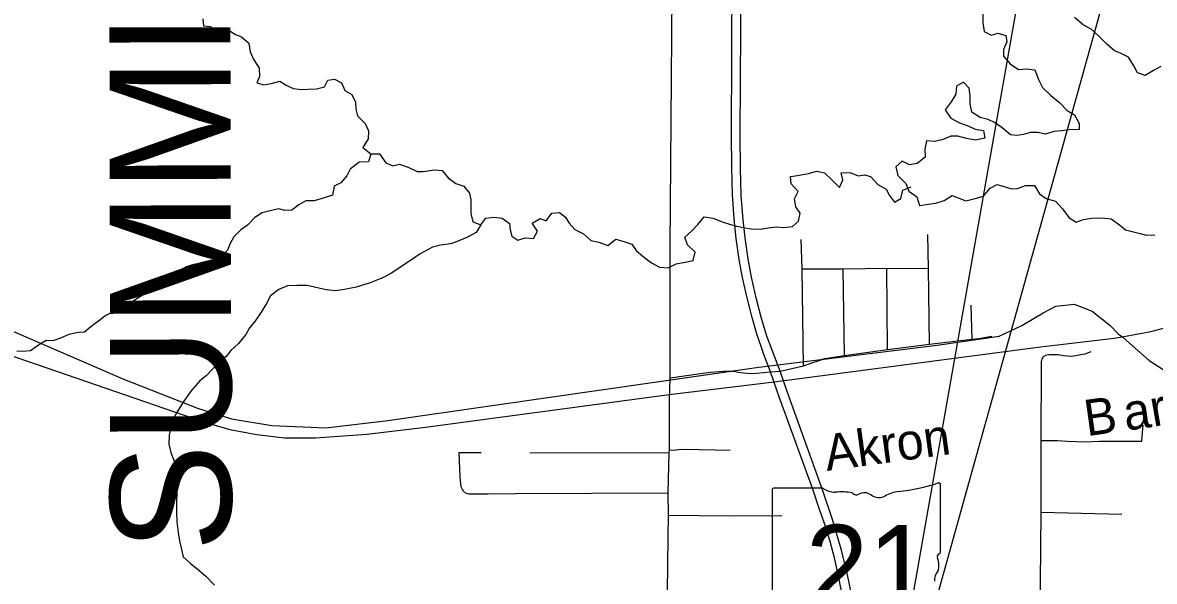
# Model space of a CAD drawing. Extents: x 0 to 34, y -5 to 22.
# Drawn here: x 4.064 to 5.836, y 18.02 to 18.894 of the extents above; entities that cross this region are included whole.
import ezdxf

# ---------------------------------------------------------------- set-up
doc = ezdxf.new("R2010")
doc.units = 0
for name, color, linetype in [('GM_X_City_Street', 7, 'Continuous'), ('GM_X_County_Road', 7, 'Continuous'), ('GM_X_County_Text', 7, 'Continuous'), ('GM_X_Major_Lake', 7, 'Continuous'), ('GM_X_Minor_River', 7, 'Continuous'), ('GM_X_Rail_Line', 7, 'Continuous'), ('GM_X_Rail_Line_Text', 7, 'Continuous'), ('GM_X_State_Location', 7, 'Continuous'), ('GM_X_State_Route', 7, 'Continuous'), ('GM_X_State_Shield', 7, 'Continuous'), ('SH_Text', 7, 'Continuous')]:
    doc.layers.add(name, color=color, linetype=linetype)

msp = doc.modelspace()

# ---------------------------------------------------------------- linework, layer by layer
at = {"layer": 'GM_X_City_Street'}
for p, q in [((5.3507, 18.3734), (5.3486, 18.5091)), ((5.4178, 18.3829), (5.4166, 18.5098)), ((5.5482, 18.452), (5.5499, 18.399)), ((4.7473, 18.2216), (4.7817, 18.2216)), ((4.8577, 18.2212), (5.076, 18.2214)), ((5.6581, 18.1281), (5.7846, 18.1252))]:
    msp.add_line(p, q, dxfattribs=at)
for points in [[(5.2863, 18.3573), (5.2842, 18.5091), (5.2828, 18.5548)], [(5.4836, 18.3912), (5.4822, 18.5096), (5.4807, 18.5626)], [(5.2842, 18.5091), (5.3486, 18.5091), (5.4166, 18.5098), (5.4822, 18.5096)], [(5.0777, 18.3384), (5.1213, 18.3448), (5.1409, 18.3474), (5.1542, 18.3483), (5.1618, 18.3488), (5.1686, 18.3486), (5.1771, 18.3486), (5.1847, 18.3474), (5.1923, 18.3464), (5.203, 18.345), (5.2127, 18.3455), (5.2346, 18.3475), (5.2498, 18.349), (5.2863, 18.3573), (5.2991, 18.3618), (5.3093, 18.3651), (5.3195, 18.3685), (5.3507, 18.3734), (5.4178, 18.3829), (5.4836, 18.3912), (5.5499, 18.399), (5.5608, 18.3999), (5.5809, 18.4033)], [(5.656, 17.6203), (5.6561, 17.7219), (5.6565, 17.8103), (5.6565, 17.9139), (5.6572, 18.0186), (5.6581, 18.1281), (5.6584, 18.2401), (5.6588, 18.359), (5.6591, 18.364), (5.66, 18.3682), (5.6621, 18.3715)], [(5.6621, 18.3715), (5.6657, 18.3737), (5.6702, 18.3751), (5.6771, 18.3751), (5.6851, 18.3746), (5.6932, 18.3734), (5.6993, 18.373), (5.7052, 18.3725), (5.7124, 18.3734), (5.7206, 18.3746), (5.727, 18.376), (5.7365, 18.3796)], [(5.8161, 18.2391), (5.8163, 18.2465), (5.8182, 18.2643)], [(5.6584, 18.2401), (5.6837, 18.2401), (5.6991, 18.2391), (5.728, 18.2382), (5.7498, 18.2391), (5.8161, 18.2391)], [(4.7548, 18.16), (4.7525, 18.1634), (4.7506, 18.1679), (4.7492, 18.1773), (4.749, 18.1835), (4.7473, 18.2216)], [(5.0763, 18.2257), (5.0831, 18.2254), (5.0905, 18.2261), (5.099, 18.2266), (5.1717, 18.2249)], [(4.7548, 18.16), (4.7582, 18.1579), (4.7625, 18.157), (4.7928, 18.157), (4.8357, 18.1574), (5.0746, 18.1584)], [(5.0751, 18.1236), (5.1705, 18.1226), (5.2522, 18.1229)]]:
    msp.add_lwpolyline(points, dxfattribs=at)
at = {"layer": 'GM_X_County_Road'}
msp.add_lwpolyline([(5.0725, 17.9168), (5.0746, 18.0892), (5.0751, 18.1236), (5.0746, 18.1584), (5.076, 18.2214), (5.0763, 18.2257), (5.0765, 18.3047), (5.0777, 18.3384), (5.0777, 18.5427), (5.0793, 18.7403), (5.0805, 18.9401), (5.0808, 19.1246), (5.081, 19.4273), (5.0819, 19.5963), (5.0824, 19.6307), (5.0824, 19.8505), (5.0836, 20.0558), (5.0846, 20.0998), (5.0842, 20.1129), (5.0864, 20.3819), (5.0857, 20.5652), (5.085, 20.7499), (5.0856, 20.9)], dxfattribs=at)
at = {"layer": 'GM_X_Major_Lake'}
for points in [[(5.5671, 18.9078), (5.5671, 18.8941), (5.5691, 18.8801), (5.5801, 18.8744), (5.5907, 18.8775), (5.6029, 18.8738), (5.6048, 18.8643), (5.5996, 18.8521), (5.5993, 18.8418), (5.6099, 18.8297), (5.6229, 18.8207), (5.6361, 18.8219), (5.6486, 18.8205), (5.654, 18.8053), (5.6605, 18.7924), (5.6727, 18.7807), (5.6876, 18.7686), (5.699, 18.7565), (5.7104, 18.7501), (5.7177, 18.7365), (5.7177, 18.7266), (5.7056, 18.7269), (5.6904, 18.7249), (5.6779, 18.7237), (5.6651, 18.7198), (5.6537, 18.7224), (5.6415, 18.722), (5.6309, 18.7192), (5.62, 18.7173), (5.6105, 18.7187), (5.5972, 18.7293), (5.5861, 18.7376), (5.5755, 18.7425), (5.5626, 18.7458), (5.5496, 18.7541), (5.5473, 18.767), (5.5472, 18.7796), (5.5457, 18.7914), (5.5365, 18.8012), (5.5256, 18.7947), (5.5249, 18.7821), (5.5173, 18.7703), (5.5083, 18.7577), (5.5167, 18.7448), (5.5304, 18.7373), (5.5452, 18.7324), (5.5551, 18.7275), (5.568, 18.7253), (5.5703, 18.7132), (5.5556, 18.7104), (5.5415, 18.713), (5.5279, 18.7164), (5.5169, 18.7163), (5.5036, 18.7105), (5.4907, 18.7082), (5.4786, 18.7092), (5.476, 18.6963), (5.4768, 18.6834), (5.464, 18.6738), (5.4523, 18.6714), (5.4409, 18.6775), (5.4307, 18.6686), (5.4341, 18.655), (5.4463, 18.6425), (5.4513, 18.6304), (5.4639, 18.6217), (5.4677, 18.608), (5.4814, 18.61), (5.4935, 18.6116), (5.5064, 18.6159), (5.5188, 18.6239), (5.5283, 18.6202), (5.5405, 18.6153)], [(5.8457, 18.8254), (5.8344, 18.8193), (5.8212, 18.8116), (5.809, 18.8157), (5.8036, 18.8267), (5.7952, 18.8399), (5.7827, 18.8463), (5.7732, 18.8501), (5.761, 18.8603), (5.7477, 18.8739), (5.7366, 18.8841), (5.7241, 18.8909), (5.7104, 18.9022)], [(5.5405, 18.6153), (5.5549, 18.6188), (5.5681, 18.6227), (5.5787, 18.6349), (5.5896, 18.6411), (5.6022, 18.6373), (5.6117, 18.634), (5.6211, 18.6344), (5.634, 18.6394), (5.648, 18.6391), (5.6557, 18.6262), (5.6663, 18.6187), (5.6807, 18.615), (5.6918, 18.6029), (5.7017, 18.5892), (5.7131, 18.5821), (5.7245, 18.5859), (5.737, 18.5883), (5.7472, 18.5887), (5.7582, 18.5884), (5.7681, 18.587), (5.781, 18.5775), (5.7905, 18.57), (5.803, 18.567), (5.8133, 18.5644), (5.8232, 18.5618), (5.8364, 18.5619)]]:
    msp.add_lwpolyline(points, dxfattribs=at)
at = {"layer": 'GM_X_Minor_River'}
for points in [[(4.3461, 18.8999), (4.347, 18.8893), (4.3587, 18.8879), (4.3629, 18.8784), (4.3732, 18.8735), (4.3837, 18.8846), (4.3971, 18.8755), (4.4066, 18.8718), (4.418, 18.862), (4.4203, 18.8483), (4.4261, 18.8358), (4.4341, 18.8229), (4.4345, 18.81), (4.4304, 18.8001), (4.4414, 18.7967), (4.4528, 18.7987), (4.4664, 18.8026), (4.4767, 18.7965), (4.4873, 18.7913), (4.5006, 18.7895), (4.5104, 18.7899), (4.5241, 18.7904), (4.5366, 18.7935), (4.5418, 18.8042), (4.5524, 18.8057), (4.5631, 18.8001), (4.5685, 18.788), (4.5791, 18.7819), (4.5852, 18.7698), (4.5853, 18.7588), (4.5884, 18.7482), (4.6002, 18.7364), (4.6052, 18.7247), (4.6048, 18.7125), (4.5966, 18.6988), (4.6091, 18.689), (4.6224, 18.6887), (4.6323, 18.675), (4.6437, 18.6702), (4.6539, 18.6729), (4.6684, 18.6673), (4.6813, 18.6613), (4.6908, 18.6613), (4.7089, 18.6637), (4.7207, 18.663), (4.7302, 18.6513), (4.742, 18.6426), (4.7546, 18.6385), (4.7633, 18.6275), (4.7657, 18.6169), (4.7657, 18.6062), (4.7654, 18.5956), (4.7689, 18.5827), (4.781, 18.5778), (4.7889, 18.5881), (4.8014, 18.5897), (4.8147, 18.5883), (4.8261, 18.5796), (4.8273, 18.5701), (4.8296, 18.5602), (4.8391, 18.5538)], [(4.6091, 18.689), (4.6054, 18.6764), (4.5906, 18.6756), (4.5766, 18.6648), (4.5714, 18.6545), (4.562, 18.6435), (4.5518, 18.6381), (4.5488, 18.624), (4.5344, 18.6193), (4.5204, 18.6151), (4.5075, 18.6154), (4.4962, 18.6092), (4.4852, 18.6008), (4.4742, 18.6004), (4.4648, 18.6026), (4.4492, 18.5991), (4.439, 18.5967), (4.4273, 18.5891), (4.416, 18.5772), (4.4054, 18.5699), (4.3948, 18.5592), (4.3888, 18.5485), (4.3847, 18.5379), (4.3749, 18.5272), (4.3605, 18.521), (4.3488, 18.519), (4.3321, 18.5159), (4.32, 18.512), (4.3064, 18.5043), (4.2928, 18.4932), (4.2834, 18.4837), (4.2702, 18.4745), (4.2565, 18.4702), (4.2399, 18.4602), (4.2263, 18.4495), (4.2154, 18.443), (4.2029, 18.4406), (4.1927, 18.4348), (4.1828, 18.4268), (4.1711, 18.4188), (4.1609, 18.4099), (4.1511, 18.4091), (4.1363, 18.4064), (4.1235, 18.4002), (4.1114, 18.3964), (4.1007, 18.397), (4.0905, 18.3905), (4.0762, 18.3806), (4.0644, 18.3793), (4.055, 18.3801)], [(4.8391, 18.5538), (4.8505, 18.5573), (4.8634, 18.5562), (4.8698, 18.5681), (4.8617, 18.5806), (4.8742, 18.5875), (4.8837, 18.5841), (4.8924, 18.596), (4.9045, 18.5968), (4.914, 18.59), (4.9194, 18.5801), (4.9285, 18.5703), (4.9418, 18.5635), (4.9536, 18.553), (4.9661, 18.5508), (4.9798, 18.5455), (4.9923, 18.5551), (5.0037, 18.5521), (5.0177, 18.5473), (5.0246, 18.5374), (5.0352, 18.528), (5.0486, 18.5182), (5.0611, 18.5114), (5.0744, 18.5107), (5.0872, 18.5169), (5.1009, 18.5192), (5.1134, 18.522), (5.1167, 18.5349), (5.1045, 18.5466), (5.1007, 18.5584), (5.1116, 18.5683), (5.121, 18.5783), (5.1308, 18.5901), (5.1449, 18.5883), (5.1589, 18.5827), (5.1722, 18.5782), (5.1817, 18.5756), (5.1923, 18.5734), (5.2045, 18.5715), (5.2185, 18.5712), (5.231, 18.5732), (5.2439, 18.5744), (5.2553, 18.5737), (5.2689, 18.5753), (5.2787, 18.5834), (5.2813, 18.5959), (5.2744, 18.6058), (5.2721, 18.6183), (5.2781, 18.6301), (5.267, 18.6418), (5.2662, 18.6536), (5.2768, 18.6548), (5.2939, 18.658), (5.3064, 18.6618), (5.3193, 18.6589), (5.3311, 18.6475), (5.3425, 18.6362), (5.3481, 18.648), (5.345, 18.659), (5.3594, 18.6595), (5.372, 18.6542), (5.3818, 18.6562), (5.3913, 18.6532), (5.4024, 18.6407), (5.4157, 18.6336), (5.421, 18.6234), (5.429, 18.6131), (5.4389, 18.6189), (5.4418, 18.6322), (5.4547, 18.6372)], [(4.781, 18.5778), (4.7739, 18.566), (4.7595, 18.5579), (4.7466, 18.5525), (4.7342, 18.5479), (4.7183, 18.5459), (4.7054, 18.5428), (4.6865, 18.5324), (4.6729, 18.5232), (4.6544, 18.5109), (4.6415, 18.5021), (4.626, 18.4944), (4.6082, 18.4871), (4.5863, 18.4801), (4.5677, 18.4766), (4.553, 18.4746), (4.5389, 18.476), (4.5093, 18.4827), (4.493, 18.483), (4.4786, 18.4825), (4.465, 18.4767), (4.4518, 18.4664), (4.4458, 18.4546), (4.4375, 18.4412), (4.4273, 18.4263), (4.4191, 18.4164), (4.4134, 18.4061), (4.4017, 18.392), (4.39, 18.3813), (4.3825, 18.3717), (4.3719, 18.3629), (4.3606, 18.3514), (4.3512, 18.3415), (4.3414, 18.3335), (4.3274, 18.3174), (4.3154, 18.3002), (4.306, 18.2853), (4.2981, 18.2712), (4.2959, 18.2598), (4.2933, 18.2488), (4.293, 18.2343), (4.2957, 18.2214), (4.3022, 18.2055), (4.3061, 18.1945), (4.3065, 18.185), (4.3058, 18.1717), (4.3051, 18.1591), (4.3048, 18.1432), (4.3049, 18.1276), (4.3053, 18.1131), (4.3073, 18.0964), (4.3093, 18.0831), (4.3124, 18.0698), (4.3155, 18.0581), (4.3265, 18.0479), (4.3364, 18.0399), (4.3509, 18.0278), (4.3642, 18.0139)]]:
    msp.add_lwpolyline(points, dxfattribs=at)
at = {"layer": 'GM_X_Rail_Line'}
for points in [[(4.0057, 18.4294), (4.2206, 18.3367), (4.3375, 18.2907), (4.3907, 18.2743), (4.4543, 18.2638), (4.5384, 18.2599), (4.6355, 18.2717), (5.2165, 18.3551), (5.4955, 18.3893), (5.5926, 18.4037), (5.6281, 18.4201), (5.6616, 18.4398), (5.6812, 18.4503), (5.7101, 18.4536), (5.7384, 18.4424), (5.7659, 18.4208), (5.7795, 18.4068)], [(4.0092, 18.3859), (4.347, 18.2697), (4.3882, 18.2573), (4.4307, 18.2497), (4.4739, 18.2442), (4.5226, 18.2442), (4.6029, 18.2501), (4.6948, 18.2613), (5.0762, 18.3125), (5.2404, 18.3319), (5.6575, 18.3867), (5.7728, 18.4004), (5.7853, 18.4026), (5.8298, 18.4107), (5.8836, 18.4248)], [(5.7795, 18.4068), (5.7859, 18.4025), (5.7918, 18.3966), (5.8276, 18.3656), (5.871, 18.3374), (6.0377, 18.2586), (6.5899, 18.0575), (7.0082, 17.9114), (7.1542, 18.0022), (7.3134, 18.0831), (7.525, 18.1436)]]:
    msp.add_lwpolyline(points, dxfattribs=at)
at = {"layer": 'GM_X_State_Route'}
for points in [[(5.3493, 17.987), (5.34, 18.0332), (5.3347, 18.0567), (5.3279, 18.0821), (5.3185, 18.1118), (5.3115, 18.1324), (5.3009, 18.1643), (5.2488, 18.3073), (5.2346, 18.3475), (5.2242, 18.3751), (5.2128, 18.4089), (5.2061, 18.4329), (5.1974, 18.4655), (5.1907, 18.4951), (5.1855, 18.5235), (5.181, 18.5563), (5.1778, 18.5869), (5.1749, 18.6253), (5.1739, 18.6669), (5.1736, 18.7198), (5.1747, 18.9685)], [(5.3656, 17.98), (5.3554, 18.0301), (5.3456, 18.0685), (5.3317, 18.1169), (5.3159, 18.1632), (5.2606, 18.3169), (5.2498, 18.349), (5.229, 18.4035), (5.2206, 18.4313), (5.2126, 18.4613), (5.2051, 18.4956), (5.1998, 18.5243), (5.1948, 18.5575), (5.1916, 18.5857), (5.1888, 18.6241), (5.1877, 18.6657), (5.1874, 18.7186), (5.1885, 18.9673)]]:
    msp.add_lwpolyline(points, dxfattribs=at)
at = {"layer": 'GM_X_State_Shield'}
for p, q in [((5.237, 18.1623), (5.237, 17.9622)), ((5.3168, 18.1658), (5.2396, 18.1658)), ((5.5007, 18.0661), (5.5007, 18.1708)), ((5.5006, 18.0661), (5.5007, 18.0661))]:
    msp.add_line(p, q, dxfattribs=at)
for centre, radius, start, end in [((5.24, 18.1628), 0.00305, 98.1301, 188.1301), ((5.3352, 18.189), 0.0296, 231.6195, 271.1119), ((5.345, 18.0534), 0.1064, 80.4867, 94.9883), ((5.3692, 18.1638), 0.00855, 219.7921, 297.1024), ((5.3817, 18.1407), 0.0178, 54.4667, 119.1411), ((5.4424, 18.1047), 0.0563, 97.3462, 120.7689), ((5.4067, 18.4386), 0.2796, 275.8445, 288.9065), ((5.4977, 18.1712), 0.00294, 351.8621, 97.738), ((5.4046, 18.1724), 0.0214, 233.8562, 294.8282), ((5.5, 18.0584), 0.00454, 107.944, 210.337), ((5.4711, 18.0451), 0.0273, 340.033, 23.6496), ((5.4975, 18.0657), 0.00314, 289.6038, 7.7341), ((5.5112, 18.0223), 0.0198, 136.8065, 186.9296)]:
    msp.add_arc(centre, radius, start, end, dxfattribs=at)
at = {"layer": 'SH_Text'}
msp.add_lwpolyline([(5.7495, 19.6552), (5.3906, 17.6203), (5.7495, 18.9062)], close=True, dxfattribs=at)

# ---------------------------------------------------------------- texts
at = {"layer": 'GM_X_County_Text'}
msp.add_text('SUMMIT COUNTY', height=0.189394, rotation=90.0981, dxfattribs=at).set_placement((4.3907, 18.0662))
at = {"layer": 'GM_X_Rail_Line_Text'}
for s, height, rotation, p in [('B', 0.0566, 7.9588, (5.7297, 18.2469)), ('a', 0.0566, 8.1297, (5.791, 18.2555)), ('r', 0.0566, 9.9837, (5.8334, 18.2616)), ('Akron', 0.05663, 7.7902, (5.3229, 18.1925))]:
    msp.add_text(s, height=height, rotation=rotation, dxfattribs=at).set_placement(p)
at = {"layer": 'GM_X_State_Location'}
msp.add_text('21', height=0.000189, rotation=0, dxfattribs=at).set_placement((5.3182, 18.0352))
for s, p in [('s', (5.3659, 18.049)), ('r', (5.3658, 18.049))]:
    msp.add_text(s, height=0.000189, dxfattribs=at).set_placement(p)
at = {"layer": 'GM_X_State_Shield'}
msp.add_text('21', height=0.13184, dxfattribs=at).set_placement((5.2897, 17.9763))

doc.saveas('drawing.dxf')
